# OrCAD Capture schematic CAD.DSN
size A
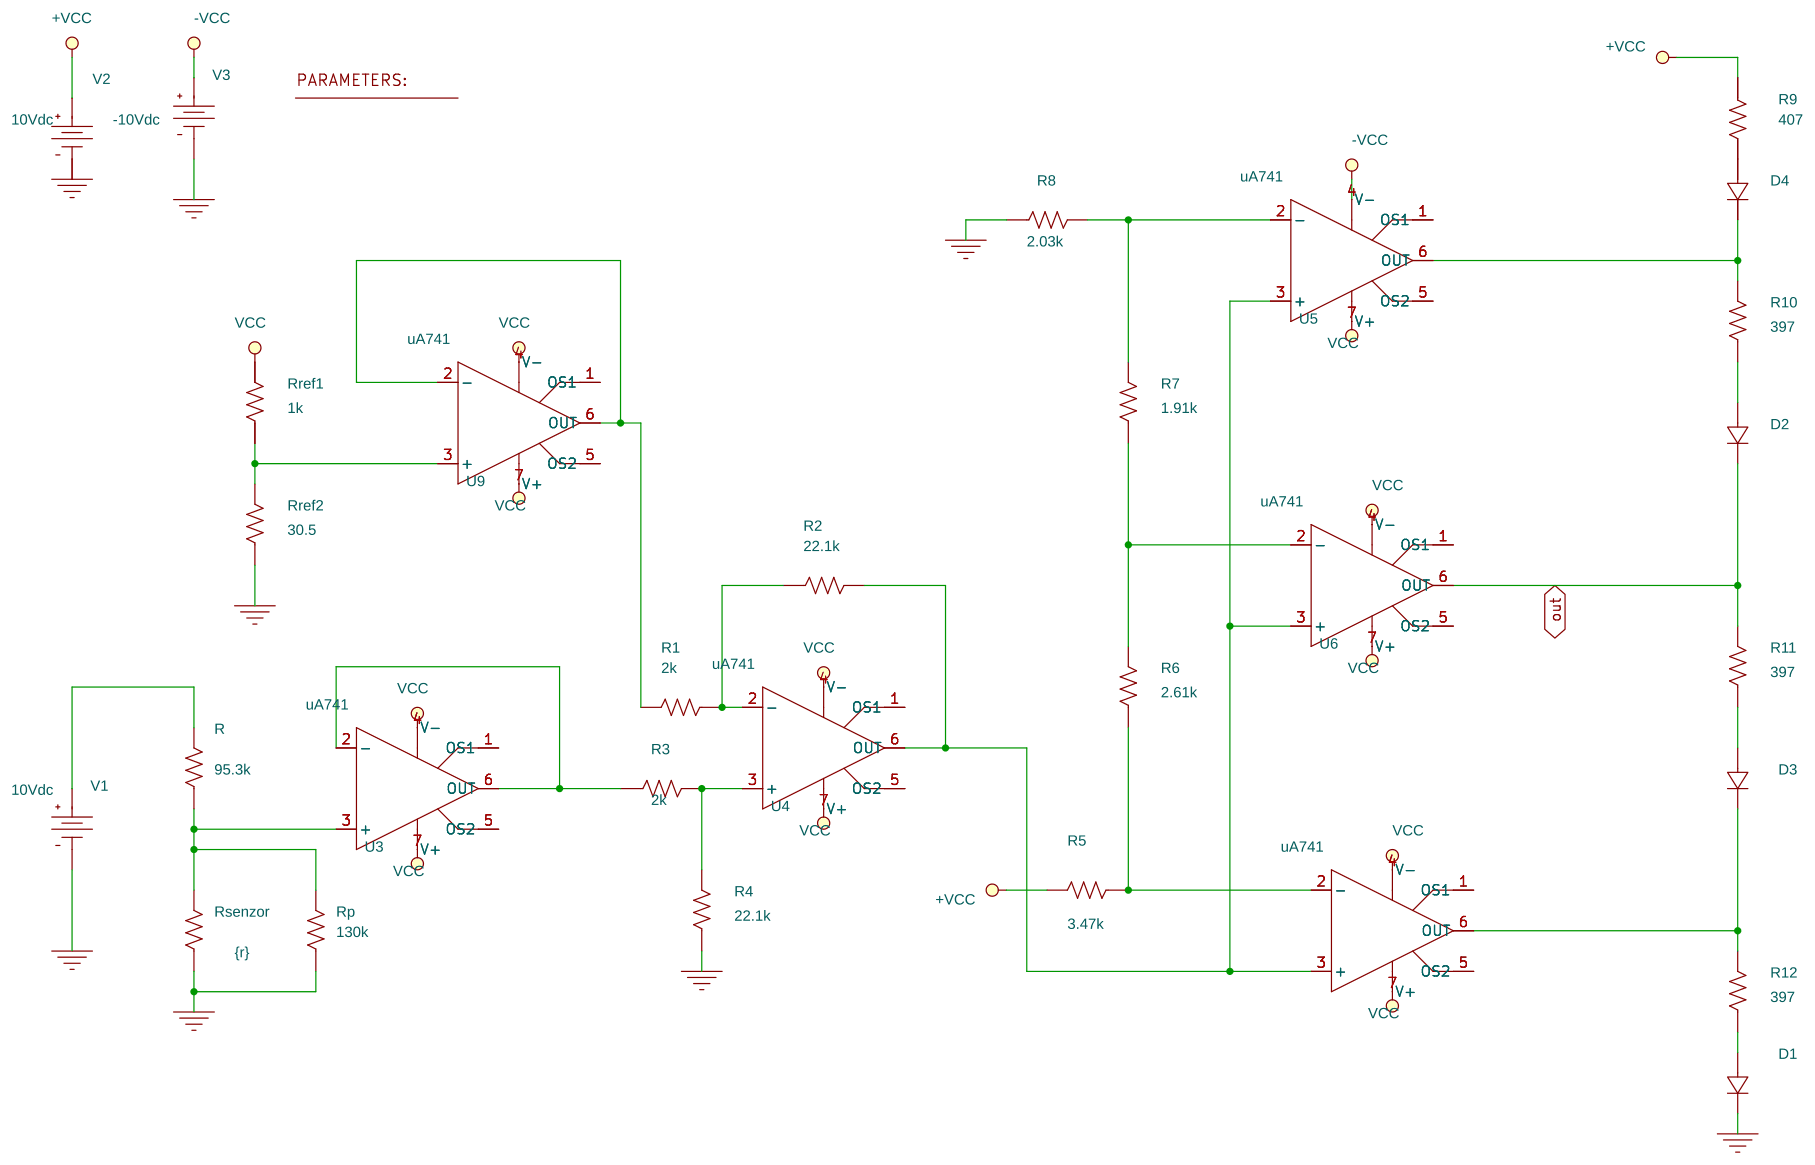
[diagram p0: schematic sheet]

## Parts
1  PARAM
D1  Dbreak
D2  Dbreak
D3  Dbreak
D4  Dbreak
R  95.3k  [AXRC05]
R1  2k  [AXRC05]
R2  22.1k  [AXRC05]
R3  2k  [AXRC05]
R4  22.1k  [AXRC05]
R5  3.47k  [AXRC05]
R6  2.61k  [AXRC05]
R7  1.91k  [AXRC05]
R8  2.03k  [AXRC05]
R9  407  [AXRC05]
R10  397  [AXRC05]
R11  397  [AXRC05]
R12  397  [AXRC05]
Rp  130k  [AXRC05]
Rref1  1k  [AXRC05]
Rref2  30.5  [AXRC05]
Rsenzor  {r}  [AXRC05]
U3  uA741  [DIP1008W300L450]
U4  uA741  [DIP1008W300L450]
U5  uA741  [DIP1008W300L450]
U6  uA741  [DIP1008W300L450]
U7  uA741  [DIP1008W300L450]
U9  uA741  [DIP1008W300L450]
V1  VDC
V2  VDC
V3  VDC

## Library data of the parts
1 = PARAM: r: 3k
D1-D4 = Dbreak: PSpiceTemplate: D^@REFDES  %1 %2 @MODEL ?AREA/@AREA/
R R1-R4 R6-R10 Rp Rref1 Rref2 = R
R5 = R: TOLERANCE: 1%
R11 R12 = R: TOLERANCE: 0.5%
Rsenzor = R: TOLERANCE: 1
U3-U7 U9 = uA741
V1 V2 = VDC: DC: 10Vdc
V3 = VDC: DC: -10Vdc

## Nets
+VCC: R5.2 R9.1 Rref1.2 U3.7(V+) U4.7(V+) U5.7(V+) U6.7(V+) U7.7(V+) U9.7(V+) V2.0(+)
-VCC: U3.4(V-) U4.4(V-) U5.4(V-) U6.4(V-) U7.4(V-) U9.4(V-) V3.0(+)
0: D1.1(2) R4.1 R8.1 Rp.1 Rref2.1 Rsenzor.1 V1.1(-) V2.1(-) V3.1(-)
out: D2.1(2) R11.2 U6.6(OUT)
N00074: R.1 Rp.2 Rsenzor.2 U3.3(+)
N00158: R.2 V1.0(+)
N00905: R3.1 U3.2(-) U3.6(OUT)
N03129: R3.2 R4.2 U4.3(+)
N03314: R1.1 R2.1 U4.2(-)
N03336: R2.2 U4.6(OUT) U5.3(+) U6.3(+) U7.3(+)
N10276: Rref1.1 Rref2.2 U9.3(+)
N10678: R1.2 U9.2(-) U9.6(OUT)
N25274: D3.0(1) R11.1
N32663: R6.2 R7.1 U6.2(-)
N32689: R5.1 R6.1 U7.2(-)
N32734: R7.2 R8.2 U5.2(-)
N32978: D2.0(1) R10.1
N33480: D3.1(2) R12.2 U7.6(OUT)
N33484: D1.0(1) R12.1
N39825: D4.1(2) R10.2 U5.6(OUT)
N39976: D4.0(1) R9.2

Not connected (* = marked no-connect by the designer): U3 1(OS1) 5(OS2); U4 1(OS1) 5(OS2); U5 1(OS1) 5(OS2); U6 1(OS1) 5(OS2); U7 1(OS1) 5(OS2); U9 1(OS1) 5(OS2)
